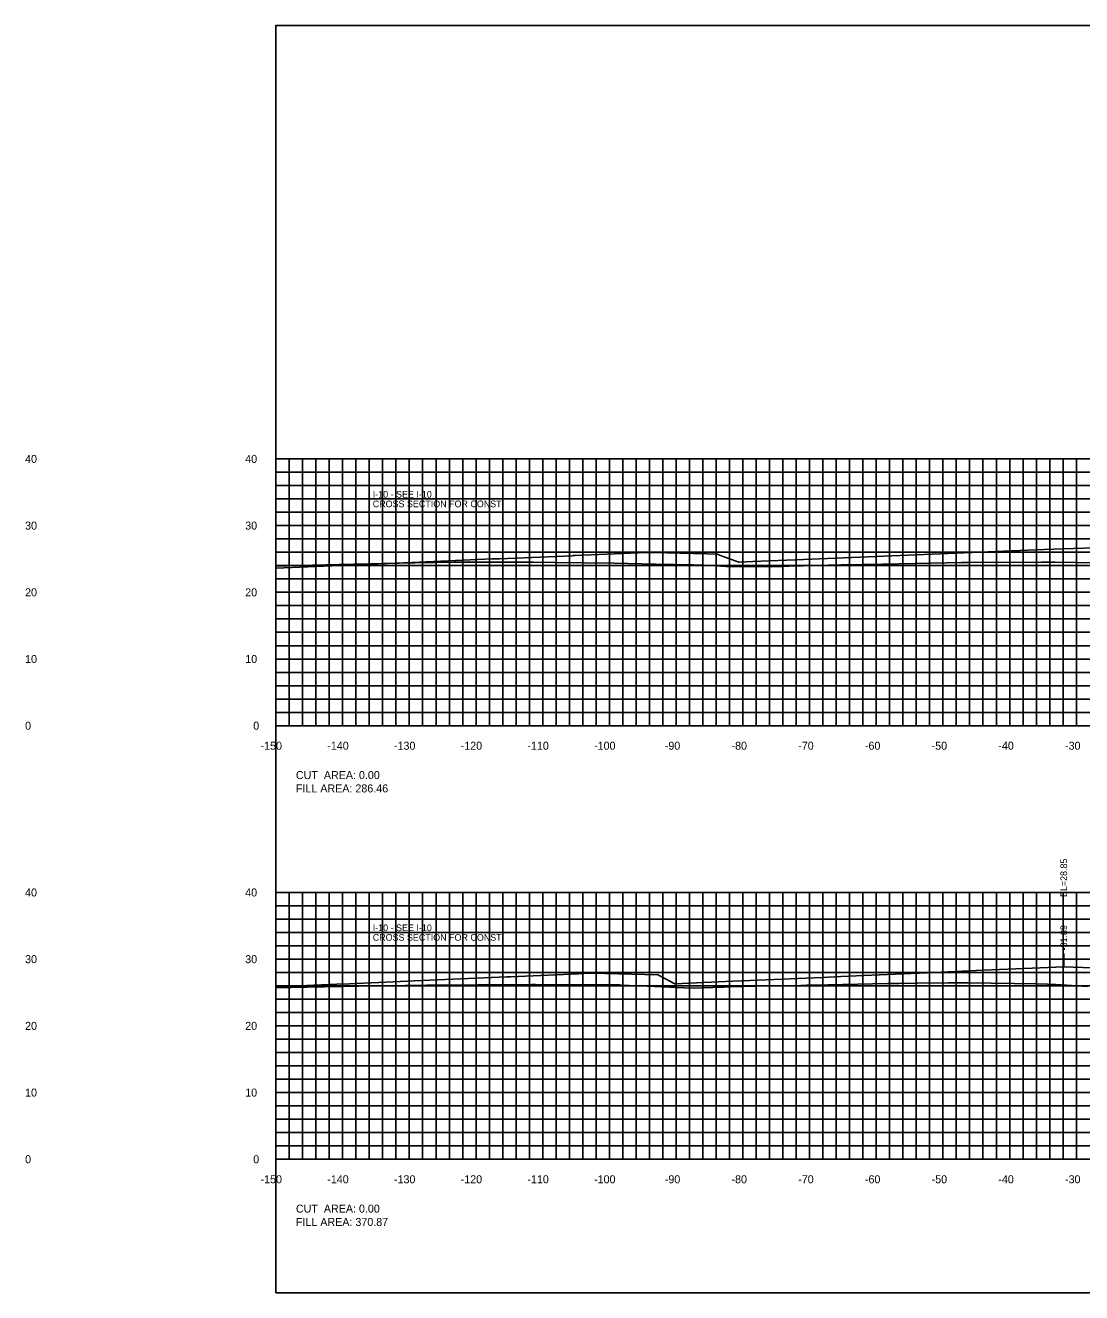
# Model space of a CAD drawing. Extents: x 1797652 to 1804145, y 245981 to 250269.
# Drawn here: x 1803463.4 to 1803621.8, y 250079.4 to 250269.4 of the extents above; entities that cross this region are included whole.
import ezdxf

# ---------------------------------------------------------------- set-up
doc = ezdxf.new("R2010")
doc.units = 0
for name, color, linetype in [('10', 7, 'Continuous'), ('3', 7, 'Continuous'), ('31', 7, 'Continuous'), ('60', 7, 'Continuous'), ('ANNO-TXT', 7, 'Continuous'), ('CL-CNST', 7, 'Continuous'), ('Level 62', 7, 'Continuous'), ('M-ROADS', 7, 'Continuous')]:
    doc.layers.add(name, color=color, linetype=linetype)

msp = doc.modelspace()

# ---------------------------------------------------------------- linework, layer by layer
msp.add_line((1803619.11, 250128.28), (1803619.11, 250130.28))
msp.add_lwpolyline([(1803501, 250079.43), (1803801, 250079.43), (1803801, 250269.43), (1803501, 250269.43)], close=True)
at = {"layer": '60'}
for p, q in [((1803500.94, 250204.43), (1803501, 250204.43)), ((1803501, 250164.43), (1803501, 250204.43)), ((1803500.94, 250194.43), (1803501, 250194.43)), ((1803500.94, 250184.43), (1803501, 250184.43)), ((1803500.94, 250174.43), (1803501, 250174.43)), ((1803500.94, 250164.43), (1803501, 250164.43)), ((1803501, 250164.43), (1803801, 250164.43)), ((1803501, 250164.37), (1803501, 250164.43)), ((1803511, 250164.37), (1803511, 250164.43)), ((1803521, 250164.37), (1803521, 250164.43)), ((1803531, 250164.37), (1803531, 250164.43)), ((1803541, 250164.37), (1803541, 250164.43)), ((1803551, 250164.37), (1803551, 250164.43)), ((1803561, 250164.37), (1803561, 250164.43)), ((1803571, 250164.37), (1803571, 250164.43)), ((1803581, 250164.37), (1803581, 250164.43)), ((1803591, 250164.37), (1803591, 250164.43)), ((1803601, 250164.37), (1803601, 250164.43)), ((1803611, 250164.37), (1803611, 250164.43)), ((1803621, 250164.37), (1803621, 250164.43)), ((1803500.94, 250139.43), (1803501, 250139.43)), ((1803501, 250099.43), (1803501, 250139.43)), ((1803500.94, 250129.43), (1803501, 250129.43)), ((1803500.94, 250119.43), (1803501, 250119.43)), ((1803500.94, 250109.43), (1803501, 250109.43)), ((1803500.94, 250099.43), (1803501, 250099.43)), ((1803501, 250099.43), (1803801, 250099.43)), ((1803501, 250099.37), (1803501, 250099.43)), ((1803511, 250099.37), (1803511, 250099.43)), ((1803521, 250099.37), (1803521, 250099.43)), ((1803531, 250099.37), (1803531, 250099.43)), ((1803541, 250099.37), (1803541, 250099.43)), ((1803551, 250099.37), (1803551, 250099.43)), ((1803561, 250099.37), (1803561, 250099.43)), ((1803571, 250099.37), (1803571, 250099.43)), ((1803581, 250099.37), (1803581, 250099.43)), ((1803591, 250099.37), (1803591, 250099.43)), ((1803601, 250099.37), (1803601, 250099.43)), ((1803611, 250099.37), (1803611, 250099.43)), ((1803621, 250099.37), (1803621, 250099.43))]:
    msp.add_line(p, q, dxfattribs=at)
at = {"layer": 'CL-CNST'}
for points in [[(1803501, 250188.07), (1803509.36, 250188.42), (1803512.57, 250188.56), (1803521.4, 250188.92), (1803523.54, 250189.02), (1803533.44, 250189.43), (1803534.52, 250189.47), (1803545.48, 250189.92), (1803545.5, 250189.93), (1803545.73, 250189.93), (1803545.73, 250189.93), (1803545.86, 250189.94), (1803556.49, 250190.38), (1803557.51, 250190.42), (1803565.61, 250190.19), (1803567.17, 250190.14), (1803567.66, 250189.95), (1803570.42, 250188.96), (1803572.5, 250189.05), (1803580.08, 250189.36), (1803583.69, 250189.51), (1803592.12, 250189.86), (1803596.97, 250190.05), (1803604.16, 250190.35), (1803610.09, 250190.59), (1803616.19, 250190.83), (1803623.52, 250191.12)], [(1803501, 250125.27), (1803510.15, 250125.67), (1803512.02, 250125.75), (1803522.88, 250126.22), (1803524.09, 250126.27), (1803535.61, 250126.77), (1803536.17, 250126.8), (1803546.37, 250127.24), (1803548.11, 250127.32), (1803548.24, 250127.32), (1803548.35, 250127.32), (1803558.29, 250127.06), (1803558.47, 250126.97), (1803560.8, 250125.74), (1803569.49, 250126.12), (1803570.86, 250126.18), (1803580.51, 250126.6), (1803582.92, 250126.7), (1803585.68, 250126.83), (1803594.99, 250127.23), (1803598.64, 250127.39), (1803607.05, 250127.76), (1803614.36, 250128.07), (1803619.11, 250128.28)], [(1803619.11, 250128.28), (1803629, 250127.93), (1803631, 250127.97), (1803635, 250128.06), (1803651, 250128.41), (1803659, 250128.09), (1803664.5, 250127.87), (1803715.21, 250110.97)]]:
    msp.add_lwpolyline(points, dxfattribs=at)
at = {"layer": 'Level 62'}
for p, q in [((1803501, 250204.43), (1803801, 250204.43)), ((1803501, 250164.43), (1803501, 250204.43)), ((1803503, 250164.43), (1803503, 250204.43)), ((1803505, 250164.43), (1803505, 250204.43)), ((1803507, 250164.43), (1803507, 250204.43)), ((1803509, 250164.43), (1803509, 250204.43)), ((1803511, 250164.43), (1803511, 250204.43)), ((1803513, 250164.43), (1803513, 250204.43)), ((1803515, 250164.43), (1803515, 250204.43)), ((1803517, 250164.43), (1803517, 250204.43)), ((1803519, 250164.43), (1803519, 250204.43)), ((1803521, 250164.43), (1803521, 250204.43)), ((1803523, 250164.43), (1803523, 250204.43)), ((1803525, 250164.43), (1803525, 250204.43)), ((1803527, 250164.43), (1803527, 250204.43)), ((1803529, 250164.43), (1803529, 250204.43)), ((1803531, 250164.43), (1803531, 250204.43)), ((1803533, 250164.43), (1803533, 250204.43)), ((1803535, 250164.43), (1803535, 250204.43)), ((1803537, 250164.43), (1803537, 250204.43)), ((1803539, 250164.43), (1803539, 250204.43)), ((1803541, 250164.43), (1803541, 250204.43)), ((1803543, 250164.43), (1803543, 250204.43)), ((1803545, 250164.43), (1803545, 250204.43)), ((1803547, 250164.43), (1803547, 250204.43)), ((1803549, 250164.43), (1803549, 250204.43)), ((1803551, 250164.43), (1803551, 250204.43)), ((1803553, 250164.43), (1803553, 250204.43)), ((1803555, 250164.43), (1803555, 250204.43)), ((1803557, 250164.43), (1803557, 250204.43)), ((1803559, 250164.43), (1803559, 250204.43)), ((1803561, 250164.43), (1803561, 250204.43)), ((1803563, 250164.43), (1803563, 250204.43)), ((1803565, 250164.43), (1803565, 250204.43)), ((1803567, 250164.43), (1803567, 250204.43)), ((1803569, 250164.43), (1803569, 250204.43)), ((1803571, 250164.43), (1803571, 250204.43)), ((1803573, 250164.43), (1803573, 250204.43)), ((1803575, 250164.43), (1803575, 250204.43)), ((1803577, 250164.43), (1803577, 250204.43)), ((1803579, 250164.43), (1803579, 250204.43)), ((1803581, 250164.43), (1803581, 250204.43)), ((1803583, 250164.43), (1803583, 250204.43)), ((1803585, 250164.43), (1803585, 250204.43)), ((1803587, 250164.43), (1803587, 250204.43)), ((1803589, 250164.43), (1803589, 250204.43)), ((1803591, 250164.43), (1803591, 250204.43)), ((1803593, 250164.43), (1803593, 250204.43)), ((1803595, 250164.43), (1803595, 250204.43)), ((1803597, 250164.43), (1803597, 250204.43)), ((1803599, 250164.43), (1803599, 250204.43)), ((1803601, 250164.43), (1803601, 250204.43)), ((1803603, 250164.43), (1803603, 250204.43)), ((1803605, 250164.43), (1803605, 250204.43)), ((1803607, 250164.43), (1803607, 250204.43)), ((1803609, 250164.43), (1803609, 250204.43)), ((1803611, 250164.43), (1803611, 250204.43)), ((1803613, 250164.43), (1803613, 250204.43)), ((1803615, 250164.43), (1803615, 250204.43)), ((1803617, 250164.43), (1803617, 250204.43)), ((1803619, 250164.43), (1803619, 250204.43)), ((1803621, 250164.43), (1803621, 250204.43)), ((1803501, 250202.43), (1803801, 250202.43)), ((1803501, 250200.43), (1803801, 250200.43)), ((1803501, 250198.43), (1803801, 250198.43)), ((1803501, 250196.43), (1803801, 250196.43)), ((1803501, 250194.43), (1803801, 250194.43)), ((1803501, 250192.43), (1803801, 250192.43)), ((1803501, 250190.43), (1803801, 250190.43)), ((1803501, 250188.43), (1803801, 250188.43)), ((1803501, 250186.43), (1803801, 250186.43)), ((1803501, 250184.43), (1803801, 250184.43)), ((1803501, 250182.43), (1803801, 250182.43)), ((1803501, 250180.43), (1803801, 250180.43)), ((1803501, 250178.43), (1803801, 250178.43)), ((1803501, 250176.43), (1803801, 250176.43)), ((1803501, 250174.43), (1803801, 250174.43)), ((1803501, 250172.43), (1803801, 250172.43)), ((1803501, 250170.43), (1803801, 250170.43)), ((1803501, 250168.43), (1803801, 250168.43)), ((1803501, 250166.43), (1803801, 250166.43)), ((1803501, 250164.43), (1803801, 250164.43)), ((1803501, 250139.43), (1803801, 250139.43)), ((1803501, 250099.43), (1803501, 250139.43)), ((1803503, 250099.43), (1803503, 250139.43)), ((1803505, 250099.43), (1803505, 250139.43)), ((1803507, 250099.43), (1803507, 250139.43)), ((1803509, 250099.43), (1803509, 250139.43)), ((1803511, 250099.43), (1803511, 250139.43)), ((1803513, 250099.43), (1803513, 250139.43)), ((1803515, 250099.43), (1803515, 250139.43)), ((1803517, 250099.43), (1803517, 250139.43)), ((1803519, 250099.43), (1803519, 250139.43)), ((1803521, 250099.43), (1803521, 250139.43)), ((1803523, 250099.43), (1803523, 250139.43)), ((1803525, 250099.43), (1803525, 250139.43)), ((1803527, 250099.43), (1803527, 250139.43)), ((1803529, 250099.43), (1803529, 250139.43)), ((1803531, 250099.43), (1803531, 250139.43)), ((1803533, 250099.43), (1803533, 250139.43)), ((1803535, 250099.43), (1803535, 250139.43)), ((1803537, 250099.43), (1803537, 250139.43)), ((1803539, 250099.43), (1803539, 250139.43)), ((1803541, 250099.43), (1803541, 250139.43)), ((1803543, 250099.43), (1803543, 250139.43)), ((1803545, 250099.43), (1803545, 250139.43)), ((1803547, 250099.43), (1803547, 250139.43)), ((1803549, 250099.43), (1803549, 250139.43)), ((1803551, 250099.43), (1803551, 250139.43)), ((1803553, 250099.43), (1803553, 250139.43)), ((1803555, 250099.43), (1803555, 250139.43)), ((1803557, 250099.43), (1803557, 250139.43)), ((1803559, 250099.43), (1803559, 250139.43)), ((1803561, 250099.43), (1803561, 250139.43)), ((1803563, 250099.43), (1803563, 250139.43)), ((1803565, 250099.43), (1803565, 250139.43)), ((1803567, 250099.43), (1803567, 250139.43)), ((1803569, 250099.43), (1803569, 250139.43)), ((1803571, 250099.43), (1803571, 250139.43)), ((1803573, 250099.43), (1803573, 250139.43)), ((1803575, 250099.43), (1803575, 250139.43)), ((1803577, 250099.43), (1803577, 250139.43)), ((1803579, 250099.43), (1803579, 250139.43)), ((1803581, 250099.43), (1803581, 250139.43)), ((1803583, 250099.43), (1803583, 250139.43)), ((1803585, 250099.43), (1803585, 250139.43)), ((1803587, 250099.43), (1803587, 250139.43)), ((1803589, 250099.43), (1803589, 250139.43)), ((1803591, 250099.43), (1803591, 250139.43)), ((1803593, 250099.43), (1803593, 250139.43)), ((1803595, 250099.43), (1803595, 250139.43)), ((1803597, 250099.43), (1803597, 250139.43)), ((1803599, 250099.43), (1803599, 250139.43)), ((1803601, 250099.43), (1803601, 250139.43)), ((1803603, 250099.43), (1803603, 250139.43)), ((1803605, 250099.43), (1803605, 250139.43)), ((1803607, 250099.43), (1803607, 250139.43)), ((1803609, 250099.43), (1803609, 250139.43)), ((1803611, 250099.43), (1803611, 250139.43)), ((1803613, 250099.43), (1803613, 250139.43)), ((1803615, 250099.43), (1803615, 250139.43)), ((1803617, 250099.43), (1803617, 250139.43)), ((1803619, 250099.43), (1803619, 250139.43)), ((1803621, 250099.43), (1803621, 250139.43)), ((1803501, 250137.43), (1803801, 250137.43)), ((1803501, 250135.43), (1803801, 250135.43)), ((1803501, 250133.43), (1803801, 250133.43)), ((1803501, 250131.43), (1803801, 250131.43)), ((1803501, 250129.43), (1803801, 250129.43)), ((1803501, 250127.43), (1803801, 250127.43)), ((1803501, 250125.43), (1803801, 250125.43)), ((1803501, 250123.43), (1803801, 250123.43)), ((1803501, 250121.43), (1803801, 250121.43)), ((1803501, 250119.43), (1803801, 250119.43)), ((1803501, 250117.43), (1803801, 250117.43)), ((1803501, 250115.43), (1803801, 250115.43)), ((1803501, 250113.43), (1803801, 250113.43)), ((1803501, 250111.43), (1803801, 250111.43)), ((1803501, 250109.43), (1803801, 250109.43)), ((1803501, 250107.43), (1803801, 250107.43)), ((1803501, 250105.43), (1803801, 250105.43)), ((1803501, 250103.43), (1803801, 250103.43)), ((1803501, 250101.43), (1803801, 250101.43)), ((1803501, 250099.43), (1803801, 250099.43))]:
    msp.add_line(p, q, dxfattribs=at)
at = {"layer": 'M-ROADS'}
for points in [[(1803501, 250188.33), (1803504.5, 250188.43), (1803510.47, 250188.58), (1803514.86, 250188.69), (1803521.83, 250188.83), (1803527.79, 250188.95), (1803532.02, 250188.94), (1803539.59, 250188.93), (1803542.8, 250188.89), (1803551.71, 250188.8), (1803557.91, 250188.67), (1803563.59, 250188.55), (1803564.11, 250188.52), (1803564.84, 250188.49), (1803566.92, 250188.38), (1803568.43, 250188.3), (1803571.46, 250188.28), (1803575.25, 250188.26), (1803577.07, 250188.32), (1803578.76, 250188.38), (1803579.58, 250188.41), (1803580.02, 250188.42), (1803585.72, 250188.53), (1803591.97, 250188.64), (1803596.83, 250188.74), (1803603.77, 250188.88), (1803604.98, 250188.89), (1803615.77, 250188.96), (1803617.77, 250188.93), (1803624, 250188.85)], [(1803501, 250125.18), (1803502.95, 250125.18), (1803503.31, 250125.19), (1803505.73, 250125.23), (1803515.91, 250125.42), (1803516.46, 250125.43), (1803517.08, 250125.44), (1803523.63, 250125.51), (1803527.65, 250125.55), (1803531.26, 250125.57), (1803538.21, 250125.6), (1803539.34, 250125.61), (1803539.93, 250125.61), (1803549.72, 250125.58), (1803551.53, 250125.57), (1803552.5, 250125.56), (1803552.78, 250125.55), (1803555.16, 250125.42), (1803556.65, 250125.36), (1803562.21, 250125.14), (1803563.75, 250125.08), (1803566.5, 250125.18), (1803567.68, 250125.23), (1803568.18, 250125.25), (1803568.94, 250125.28), (1803573.07, 250125.37), (1803579.7, 250125.5), (1803580.54, 250125.52), (1803581.07, 250125.53), (1803583.75, 250125.59), (1803592.67, 250125.78), (1803594.42, 250125.79), (1803597.18, 250125.82), (1803601.82, 250125.86), (1803604.78, 250125.89), (1803615.12, 250125.71), (1803616.69, 250125.69), (1803617.75, 250125.62), (1803617.94, 250125.62), (1803622.69, 250125.34)]]:
    msp.add_lwpolyline(points, dxfattribs=at)

# ---------------------------------------------------------------- texts
at = {"layer": '10'}
for s, p in [('-150', (1803498.7, 250160.83)), ('-140', (1803508.7, 250160.83)), ('-130', (1803518.7, 250160.83)), ('-120', (1803528.7, 250160.83)), ('-110', (1803538.7, 250160.83)), ('-100', (1803548.7, 250160.83)), ('-90', (1803559.3, 250160.83)), ('-80', (1803569.3, 250160.83)), ('-70', (1803579.3, 250160.83)), ('-60', (1803589.3, 250160.83)), ('-50', (1803599.3, 250160.83)), ('-40', (1803609.3, 250160.83)), ('-30', (1803619.3, 250160.83)), ('-150', (1803498.7, 250095.83)), ('-140', (1803508.7, 250095.83)), ('-130', (1803518.7, 250095.83)), ('-120', (1803528.7, 250095.83)), ('-110', (1803538.7, 250095.83)), ('-100', (1803548.7, 250095.83)), ('-90', (1803559.3, 250095.83)), ('-80', (1803569.3, 250095.83)), ('-70', (1803579.3, 250095.83)), ('-60', (1803589.3, 250095.83)), ('-50', (1803599.3, 250095.83)), ('-40', (1803609.3, 250095.83)), ('-30', (1803619.3, 250095.83))]:
    msp.add_text(s, height=1.2, dxfattribs=at).set_placement(p)
at = {"layer": '3'}
for s, p in [('I-10 - SEE I-10', (1803515.52, 250198.63)), ('CROSS SECTION FOR CONST ', (1803515.52, 250197.19)), ('CROSS SECTION FOR CONST ', (1803515.52, 250132.19)), ('I-10 - SEE I-10', (1803515.52, 250133.63))]:
    msp.add_text(s, height=1, dxfattribs=at).set_placement(p)
for s, p in [('EL=28.85', (1803619.61, 250138.75)), ('-31.89', (1803619.61, 250130.74))]:
    msp.add_text(s, height=1, rotation=90, dxfattribs=at).set_placement(p)
at = {"layer": '31'}
for s, p in [('40', (1803463.4, 250203.83)), ('40', (1803496.4, 250203.83)), ('30', (1803463.4, 250193.83)), ('30', (1803496.4, 250193.83)), ('20', (1803463.4, 250183.83)), ('20', (1803496.4, 250183.83)), ('10', (1803463.4, 250173.83)), ('10', (1803496.4, 250173.83)), ('0', (1803463.4, 250163.83)), ('0', (1803497.6, 250163.83)), ('40', (1803463.4, 250138.83)), ('40', (1803496.4, 250138.83)), ('30', (1803463.4, 250128.83)), ('30', (1803496.4, 250128.83)), ('20', (1803463.4, 250118.83)), ('20', (1803496.4, 250118.83)), ('10', (1803463.4, 250108.83)), ('10', (1803496.4, 250108.83)), ('0', (1803463.4, 250098.83)), ('0', (1803497.6, 250098.83))]:
    msp.add_text(s, height=1.2, dxfattribs=at).set_placement(p)
at = {"layer": '60'}
for p in [(1803501, 250164.43), (1803501, 250099.43)]:
    msp.add_text('-', height=0.0001, dxfattribs=at).set_placement(p)
at = {"layer": 'ANNO-TXT'}
for s, p in [('CUT  AREA: 0.00', (1803504, 250156.43)), ('FILL AREA: 286.46', (1803504, 250154.43)), ('CUT  AREA: 0.00', (1803504, 250091.43)), ('FILL AREA: 370.87', (1803504, 250089.43))]:
    msp.add_text(s, height=1.2, dxfattribs=at).set_placement(p)

doc.saveas('drawing.dxf')
